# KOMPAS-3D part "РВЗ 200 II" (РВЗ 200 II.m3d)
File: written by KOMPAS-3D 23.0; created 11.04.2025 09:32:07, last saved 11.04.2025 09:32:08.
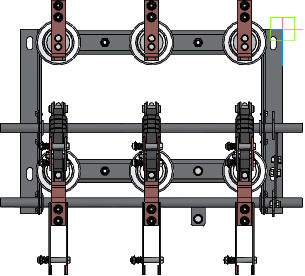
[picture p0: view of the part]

Document properties: Автор: pc; Полное имя файла: C:\Users\pc\Desktop\работа\РВЗ\3D макеты\РВЗ 200 II.m3d

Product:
- Body: Тело 1
    Масса: 0.01131
- Body: Тело 2
    Масса: 0.01131
- Body: Тело 3
    Масса: 0.01131
- Body: Тело 4
    Масса: 0.01131
- Body: Тело 5
    Масса: 0.01131
- Body: Тело 6
    Масса: 1.60238
- Body: Тело 7
    Масса: 0.011176
- Body: Тело 8
    Масса: 0.052628
- Body: Тело 9
    Масса: 0.052628
- Body: Тело 10
    Масса: 1.60238
- Part/product: РВЗ 200 II
    Масса: 3.37774

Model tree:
1. Операция без истории:1
2. Операция без истории:2
3. Операция без истории:3
4. Операция без истории:4
5. Операция без истории:5
6. Операция без истории:6
7. Операция без истории:7
8. Операция без истории:8
9. Операция без истории:9
10. Операция без истории:10
11. Поверхность без истории:1
12. Поверхность без истории:2
13. Поверхность без истории:3
14. Поверхность без истории:4
15. Поверхность без истории:5
16. Поверхность без истории:6
17. Поверхность без истории:7
18. Поверхность без истории:8
19. Поверхность без истории:9
20. Поверхность без истории:10
21. Поверхность без истории:11
22. Поверхность без истории:12
23. Поверхность без истории:13
24. Поверхность без истории:14
25. Поверхность без истории:15
26. Поверхность без истории:16
27. Поверхность без истории:17
28. Поверхность без истории:18
29. Поверхность без истории:19
30. Поверхность без истории:20
31. Поверхность без истории:21
32. Поверхность без истории:22
33. Поверхность без истории:23
34. Поверхность без истории:24
35. Поверхность без истории:25
36. Поверхность без истории:26
37. Поверхность без истории:27
38. Поверхность без истории:28
39. Поверхность без истории:29
40. Поверхность без истории:30
41. Поверхность без истории:31
42. Поверхность без истории:32
43. Поверхность без истории:33
44. Поверхность без истории:34
45. Поверхность без истории:35
46. Поверхность без истории:36
47. Поверхность без истории:37
48. Поверхность без истории:38
49. Поверхность без истории:39
50. Поверхность без истории:40
51. Поверхность без истории:41
52. Поверхность без истории:42
53. Поверхность без истории:43
54. Поверхность без истории:44
55. Поверхность без истории:45
56. Поверхность без истории:46
57. Поверхность без истории:47
58. Поверхность без истории:48
59. Поверхность без истории:49
60. Поверхность без истории:50
61. Поверхность без истории:51
62. Поверхность без истории:52
63. Поверхность без истории:53
64. Поверхность без истории:54
65. Поверхность без истории:55
66. Поверхность без истории:56
67. Поверхность без истории:57
68. Поверхность без истории:58
69. Поверхность без истории:59
70. Поверхность без истории:60
71. Поверхность без истории:61
72. Поверхность без истории:62
73. Поверхность без истории:63
74. Поверхность без истории:64
75. Поверхность без истории:65
76. Поверхность без истории:66
77. Поверхность без истории:67
78. Поверхность без истории:68
79. Поверхность без истории:69
80. Поверхность без истории:70
81. Поверхность без истории:71
82. Поверхность без истории:72
83. Поверхность без истории:73
84. Поверхность без истории:74
85. Поверхность без истории:75
86. Поверхность без истории:76
87. Поверхность без истории:77
88. Поверхность без истории:78
89. Поверхность без истории:79
90. Поверхность без истории:80
91. Поверхность без истории:81
92. Поверхность без истории:82
93. Поверхность без истории:83
94. Поверхность без истории:84
95. Поверхность без истории:85
96. Поверхность без истории:86
97. Поверхность без истории:87
98. Поверхность без истории:88
99. Поверхность без истории:89
100. Поверхность без истории:90
101. Поверхность без истории:91
102. Поверхность без истории:92
103. Поверхность без истории:93
104. Поверхность без истории:94
105. Поверхность без истории:95
106. Поверхность без истории:96
107. Поверхность без истории:97
108. Поверхность без истории:98
109. Поверхность без истории:99
110. Поверхность без истории:100
111. Поверхность без истории:101
112. Поверхность без истории:102
113. Поверхность без истории:103
114. Поверхность без истории:104
115. Поверхность без истории:105
116. Поверхность без истории:106
117. Поверхность без истории:107
118. Поверхность без истории:108
119. Поверхность без истории:109
120. Поверхность без истории:110
121. Поверхность без истории:111
122. Поверхность без истории:112
123. Поверхность без истории:113
124. Поверхность без истории:114
125. Поверхность без истории:115
126. Поверхность без истории:116
127. Поверхность без истории:117
128. Поверхность без истории:118
129. Поверхность без истории:119
130. Поверхность без истории:120
131. Поверхность без истории:121
132. Поверхность без истории:122
133. Поверхность без истории:123
134. Поверхность без истории:124
135. Поверхность без истории:125
136. Поверхность без истории:126
137. Поверхность без истории:127
138. Поверхность без истории:128
139. Поверхность без истории:129
140. Поверхность без истории:130
141. Поверхность без истории:131
142. Поверхность без истории:132
143. Поверхность без истории:133
144. Поверхность без истории:134
145. Поверхность без истории:135
146. Поверхность без истории:136
147. Поверхность без истории:137
148. Поверхность без истории:138
149. Поверхность без истории:139
150. Поверхность без истории:140
151. Поверхность без истории:141
152. Поверхность без истории:142
153. Поверхность без истории:143
154. Поверхность без истории:144
155. Поверхность без истории:145
156. Поверхность без истории:146
157. Поверхность без истории:147
158. Поверхность без истории:148
159. Поверхность без истории:149
160. Поверхность без истории:150
161. Поверхность без истории:151
162. Поверхность без истории:152
163. Поверхность без истории:153
164. Поверхность без истории:154
165. Поверхность без истории:155
166. Поверхность без истории:156
167. Поверхность без истории:157
168. Поверхность без истории:158
169. Поверхность без истории:159
170. Поверхность без истории:160
171. Поверхность без истории:161
172. Поверхность без истории:162
173. Поверхность без истории:163
174. Поверхность без истории:164
175. Поверхность без истории:165
176. Поверхность без истории:166
177. Поверхность без истории:167
178. Поверхность без истории:168
179. Поверхность без истории:169
180. Поверхность без истории:170
181. Поверхность без истории:171
182. Поверхность без истории:172
183. Поверхность без истории:173
184. Поверхность без истории:174
185. Поверхность без истории:175
186. Поверхность без истории:176
187. Поверхность без истории:177
188. Поверхность без истории:178
189. Поверхность без истории:179
190. Поверхность без истории:180
191. Поверхность без истории:181
192. Поверхность без истории:182
193. Поверхность без истории:183
194. Поверхность без истории:184
195. Поверхность без истории:185
196. Поверхность без истории:186
197. Поверхность без истории:187
198. Поверхность без истории:188
199. Поверхность без истории:189
200. Поверхность без истории:190
201. Поверхность без истории:191
202. Поверхность без истории:192
203. Поверхность без истории:193
204. Поверхность без истории:194
205. Поверхность без истории:195
206. Поверхность без истории:196
207. Поверхность без истории:197
208. Поверхность без истории:198
209. Поверхность без истории:199
210. Поверхность без истории:200
211. Поверхность без истории:201
212. Поверхность без истории:202
213. Поверхность без истории:203
214. Поверхность без истории:204
215. Поверхность без истории:205
216. Поверхность без истории:206
217. Поверхность без истории:207
218. Поверхность без истории:208
219. Поверхность без истории:209
220. Поверхность без истории:210
221. Поверхность без истории:211
222. Поверхность без истории:212
223. Поверхность без истории:213
224. Поверхность без истории:214
225. Поверхность без истории:215
226. Поверхность без истории:216
227. Поверхность без истории:217
228. Поверхность без истории:218
229. Поверхность без истории:219
230. Поверхность без истории:220
231. Поверхность без истории:221
232. Поверхность без истории:222
233. Поверхность без истории:223
234. Поверхность без истории:224
235. Поверхность без истории:225
236. Поверхность без истории:226
237. Поверхность без истории:227
238. Поверхность без истории:228
239. Поверхность без истории:229
240. Поверхность без истории:230
241. Поверхность без истории:231
242. Поверхность без истории:232
243. Поверхность без истории:233
244. Поверхность без истории:234
245. Поверхность без истории:235
246. Поверхность без истории:236
247. Поверхность без истории:237
248. Поверхность без истории:238
249. Поверхность без истории:239
250. Поверхность без истории:240
251. Поверхность без истории:241
252. Поверхность без истории:242
253. Поверхность без истории:243
254. Поверхность без истории:244
255. Поверхность без истории:245
256. Поверхность без истории:246
257. Поверхность без истории:247
258. Поверхность без истории:248
259. Поверхность без истории:249
260. Поверхность без истории:250
261. Поверхность без истории:251
262. Поверхность без истории:252
263. Поверхность без истории:253
264. Поверхность без истории:254
265. Поверхность без истории:255
266. Поверхность без истории:256
267. Поверхность без истории:257
268. Поверхность без истории:258
269. Поверхность без истории:259
270. Поверхность без истории:260
271. Поверхность без истории:261
272. Поверхность без истории:262
273. Поверхность без истории:263
274. Поверхность без истории:264
275. Поверхность без истории:265
276. Поверхность без истории:266
277. Поверхность без истории:267
278. Поверхность без истории:268
279. Поверхность без истории:269
280. Поверхность без истории:270
281. Поверхность без истории:271
282. Поверхность без истории:272
283. Поверхность без истории:273
284. Поверхность без истории:274
285. Поверхность без истории:275
286. Поверхность без истории:276
287. Поверхность без истории:277
288. Поверхность без истории:278
289. Поверхность без истории:279
290. Поверхность без истории:280
291. Поверхность без истории:281
292. Поверхность без истории:282
293. Поверхность без истории:283
294. Поверхность без истории:284
295. Поверхность без истории:285
296. Поверхность без истории:286
297. Поверхность без истории:287
298. Поверхность без истории:288
299. Поверхность без истории:289
300. Поверхность без истории:290
301. Поверхность без истории:291
302. Поверхность без истории:292
303. Поверхность без истории:293
304. Поверхность без истории:294
305. Поверхность без истории:295
306. Поверхность без истории:296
